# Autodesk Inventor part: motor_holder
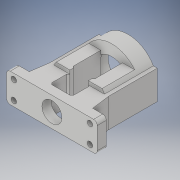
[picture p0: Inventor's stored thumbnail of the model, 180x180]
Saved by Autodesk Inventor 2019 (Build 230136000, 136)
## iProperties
Created: 2018-06
Part Number: motor_holder
Material: Generic
Document SubType Name: Modeling
Designer: felldings
Density: 1 g/cm^3
Appearance: Default
Author: felldings
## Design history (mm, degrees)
sketch "Sketch1"
  geometry: C1 r 11.1 at (0, 0); C2 r 16.1 at (0, 0); 1 further point
  constraints: 2 centre point, 2 coincident
  dimensions: "d0" = 22.2 diameter of C1; "d1" = 5 radial gap between concentric circles of C2 C1
extrude "Extrusion1" new body sketch "Sketch1" distance "d2" = 7; taper "d3" = 0 deg
sketch "Sketch2"
  geometry: C1 r 10 at (0, 0); C2 r 16.1 at (0, 0); C3 r 16.1 at (0, 0) reference; 1 further point
  constraints: 2 centre point, 2 coincident, 1 concentric
  dimensions: "d4" = 20 diameter of C1
extrude "Extrusion2" join sketch "Sketch2" distance "d5" = 2; taper "d6" = 0 deg
sketch "Sketch4"
  geometry: L1 (-12.618, 10)-(-6, 10); L2 (-12.618, -10)-(-6, -10); L3 (-6, -10)-(-6, 10); L4 (12.618, -10)-(6, -10); L5 (6, -10)-(6, 10); L6 (6, 10)-(12.618, 10); L7 (-22.61, 0)-(22.61, 0) reference; C1 r 10 at (0, 0) reference; A1 r 16.1 centre (0, 0) between (-12.618, 10) and (-12.618, -10) reference; A2 r 16.1 centre (0, 0) between (-12.618, 10) and (-12.618, -10); A3 r 16.1 centre (0, 0) between (12.618, -10) and (12.618, 10); 1 further point
  constraints: 12 end point, 8 point on circle, 3 horizontal, 2 centre point, 2 coincident, 2 equal length, 2 perpendicular, 1 point on line, 1 vertical, 1 other
  dimensions: "d8" = 20 distance of L1.end L2.end; "d9" = 12 distance between parallel lines of L5 L3
extrude "Extrusion3" join sketch "Sketch4" distance "d10" = 16; taper "d11" = 0 deg
sketch "Sketch7"
  geometry: L1 (-12.618, -10)-(-6, -10) reference; L2 (-6, -10)-(-6, 10) reference; L3 (-6, 10)-(-12.618, 10) reference; L4 (12.618, 10)-(6, 10) reference; L5 (6, 10)-(6, -10) reference; L6 (6, -10)-(12.618, -10) reference; L7 (12.618, 10)-(6, 10) reference; L8 (-12.618, 10)-(-5.1, 10); L9 (-5.1, 10)-(-5.1, -10); L10 (-6, -10)-(-12.618, -10) reference; L11 (-5.1, -10)-(-12.618, -10); L12 (12.618, 10)-(5.1, 10); L13 (5.1, 10)-(5.1, -10); L14 (5.1, -10)-(12.618, -10); L15 (12.618, -10)-(6, -10) reference; L16 (6, -10)-(12.618, -10) reference; A1 r 16.1 centre (0, 0) between (-12.618, 10) and (-12.618, -10) reference; A2 r 16.1 centre (0, 0) between (12.618, -10) and (12.618, 10) reference; A3 r 16.1 centre (0, 0) between (-12.618, 10) and (-12.618, -10) reference; A4 r 16.1 centre (0, 0) between (-12.618, 10) and (-12.618, -10); A5 r 16.1 centre (0, 0) between (12.618, -10) and (12.618, 10); 1 further point
  constraints: 12 end point, 5 point on circle, 3 collinear, 2 centre point, 2 coincident, 2 horizontal, 2 perpendicular, 1 point on line
  dimensions: "d15" = 10.2 distance between parallel lines of L13 L9
extrude "Extrusion5" join sketch "Sketch7" distance "d16" = 2; taper "d17" = 0 deg
sketch "Sketch8"
  geometry: L1 (12.618, 27)-(12.618, 27) reference; L2 (5.1, 27)-(12.618, 27) reference; L3 (5.1, 27)-(12.618, 27) reference; L4 (-12.618, 27)-(-5.1, 27) reference; L5 (-5.1, 27)-(-12.618, 27) reference; L6 (-12.618, 27)-(-12.618, 27) reference; L7 (12.618, 27)-(12.618, 27) reference; L8 (5.1, 27)-(12.618, 27) reference; L9 (5.1, 27)-(12.618, 27) reference; L10 (17.5, 37)-(25, 37); L11 (25, 37)-(25, 42); L12 (25, 42)-(-25, 42); L13 (-25, 42)-(-25, 37); L14 (-25, 37)-(-17.5, 37); L15 (-17.5, 37)-(-16.1, 27); L16 (-16.1, 0)-(-16.1, 27) reference; L17 (-16.1, 27)-(-5.1, 27); L18 (6, 27)-(6, 37); L19 (6, 37)-(-6, 37); L20 (-6, 37)-(-6, 27); L21 (0, -8.4)-(0, 50.4) reference; L22 (35, 0)-(-35, 0) reference; L23 (16.1, 27)-(12.618, 27) reference; L24 (16.1, 27)-(17.5, 37); L25 (16.1, 27)-(6, 27); 1 further point
  constraints: 24 end point, 6 point on line, 4 perpendicular, 3 collinear, 1 vertical, 2 other
  dimensions: "d18" = 50 distance of L11.end L12.end; "d19" = 35 distance of L14.end L10.start; "d20" = 42 distance between parallel lines of L22 L12; "d21" = 37 distance between parallel lines of L22 L14; "d22" = 12 distance between parallel lines of L20 L18
extrude "Extrusion6" join sketch "Sketch8" stored distance "d23" = 16; taper "d24" = 0 deg
chamfer "Chamfer1" distance "d25" = 0.3; stored, may be unused: second distance "d26" = 2, angle "d27" = 45 deg
chamfer "Chamfer3" distance "d31" = 1; stored, may be unused: second distance "d32" = 2, angle "d33" = 45 deg
chamfer "Chamfer4" distance "d34" = 0.8; stored, may be unused: second distance "d35" = 2, angle "d36" = 45 deg
sketch "Sketch9"
  geometry: C1 r 5.5 at (25, -8); 1 further point
  constraints: 1 centre point, 1 coincident
  dimensions: "d37" = 11 diameter of C1
extrude "Extrusion7" cut sketch "Sketch9" distance "d38" = 8; taper "d39" = 0 deg
sketch "Sketch10"
  geometry: 5 further points
  dimensions: "d40" = 42 distance of point (4, -13) point (46, -13); "d41" = 42 distance of point (4, -3) point (46, -3); "d42" = 10 distance of point (46, -3) point (46, -13); "d43" = 10 distance of point (4, -3) point (4, -13); "d44" = 5 vertical distance of point (25, -8) point (46, -13); "d45" = 21 horizontal distance of point (25, -8) point (46, -13); "d46" = 5 vertical distance of point (4, -3) point (25, -8); "d47" = 21 horizontal distance of point (4, -3) point (25, -8)
hole "Hole1" sketch "Sketch10" at (46, -13), (46, -3), (4, -3), (4, -13) diameter "d48" = 3; stored, may be unused: countersink angle "d52" = 90 deg, drill point angle "d54" = 118 deg; dims "d49" = 6, "d50" = 4, "d51" = 2, "d53" = 8
sketch "Sketch11"
  geometry: L1 (0, 0)-(2.128, 0) reference; L2 (0, 0)-(0, -8) reference; L3 (0, -8)-(0, -16) reference; L4 (32.2, -16)-(30.072, -16) reference; L5 (32.2, -16)-(32.2, -8) reference; L6 (32.2, -8)-(32.2, 0) reference; L7 (30.072, 0)-(32.2, 0) reference; L8 (2.128, -16)-(0, -16) reference; L9 (0, -16)-(2.128, -16); L10 (2.128, -16)-(2.128, 0); L11 (2.128, 0)-(0, 0); L12 (0, 0)-(0, -16); L13 (30.072, -16)-(32.2, -16); L14 (32.2, -16)-(32.2, 0); L15 (32.2, 0)-(30.072, 0); L16 (30.072, 0)-(30.072, -16); A1 r 16.1 centre (16.1, -8) between (2.128, 0) and (0, -8) reference; A2 r 16.1 centre (16.1, -8) between (30.072, -16) and (32.2, -8) reference; A3 r 16.1 centre (16.1, -8) between (32.2, -8) and (30.072, 0) reference; 1 further point
  constraints: 16 end point, 4 parallel, 2 horizontal, 2 perpendicular, 1 point on circle, 1 point on line
extrude "Extrusion8" join sketch "Sketch11" distance "d55" = 27; taper "d56" = 0 deg
chamfer "Chamfer5" distance "d57" = 1; stored, may be unused: second distance "d58" = 2, angle "d59" = 45 deg
fillet "Fillet1" dims "d60" = 2
body "Solid1"
node "Projected Loop2"
node "Projected Loop3"
node "Projected Loop4"
node "Projected Loop5"
node "Projected Loop6"
node "Projected Loop7"
node "Projected Loop8"
node "Projected Loop9"
